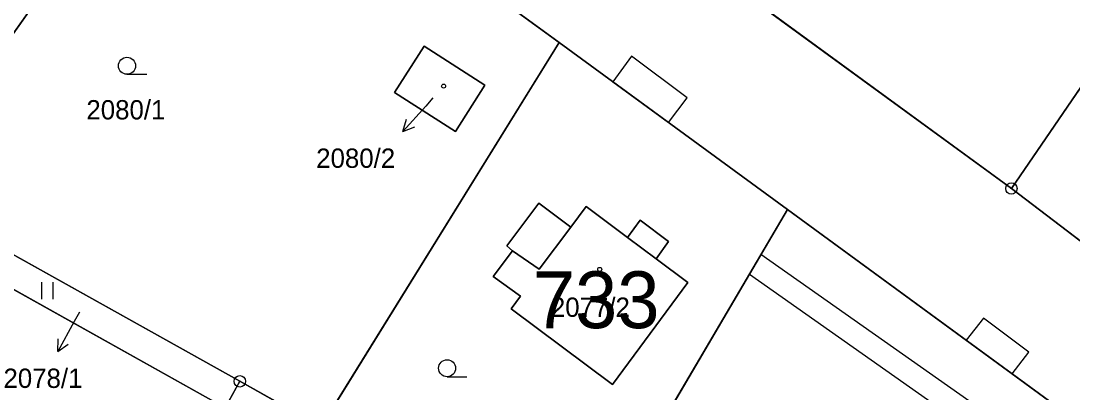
# Model space of a CAD drawing. Extents: x -689422 to -685210, y -987725 to -982160.
# Drawn here: x -687744.2 to -687651.6, y -985018.3 to -984985.6 of the extents above; entities that cross this region are included whole.
import ezdxf

# ---------------------------------------------------------------- set-up
doc = ezdxf.new("R2010")
doc.units = 0
for name, color, linetype in [('KN_Budovy', 7, 'Continuous'), ('KN_Budovy_cisla_domovni', 7, 'Continuous'), ('KN_Hranice_parcel', 7, 'Continuous'), ('KN_Hranice_parcel_vnitrni_kresba', 7, 'Continuous'), ('KN_Parcelni cisla', 7, 'Continuous'), ('KN_Parcelni cisla_sipky', 7, 'Continuous'), ('KN_Polygon parcely', 7, 'Continuous'), ('KN_POZEMKY_OSTATNI PLOCHA', 7, 'Continuous'), ('KN_POZEMKY_TTP', 7, 'Continuous'), ('KN_POZEMKY_ZAHRADA', 7, 'Continuous'), ('KN_POZEMKY_ZASTAVENA PLOCHA', 7, 'Continuous'), ('KN_VYUZITI_16_ostatni plocha_silnice', 7, 'Continuous'), ('KN_Věcná břemena k části', 7, 'Continuous'), ('KN_Značky bodu BP', 7, 'Continuous'), ('KN_Značky budov', 7, 'Continuous'), ('KN_Značky kultur', 7, 'Continuous')]:
    doc.layers.add(name, color=color, linetype=linetype)

msp = doc.modelspace()

# ---------------------------------------------------------------- linework, layer by layer
at = {"layer": 'KN_Budovy'}
for points in [[(-687711.29, -984991.84), (-687705.93, -984995.27), (-687703.33, -984991.22), (-687708.69, -984987.78)], [(-687690.78, -985004.6), (-687694.41, -985001.88), (-687695.77, -985003.69), (-687698.56, -985007.39), (-687700.9, -985005.77), (-687702.61, -985008.04), (-687700.21, -985009.76), (-687701.03, -985010.87), (-687692.1, -985017.54), (-687685.47, -985008.57), (-687688.27, -985006.48)]]:
    msp.add_lwpolyline(points, close=True, dxfattribs=at)
at = {"layer": 'KN_Hranice_parcel'}
for p, q in [((-687728.9, -984964.08), (-687696.81, -984987.44)), ((-687656.99, -985000.3), (-687686.61, -984978.67)), ((-687717.76, -985021.26), (-687696.81, -984987.44)), ((-687696.81, -984987.44), (-687676.7, -985002.14)), ((-687638.33, -985014.48), (-687656.99, -985000.3)), ((-687676.7, -985002.14), (-687693.14, -985030.09)), ((-687676.7, -985002.14), (-687634.28, -985033.15)), ((-687749.74, -985003.39), (-687724.91, -985017.26)), ((-687752.64, -985004.81), (-687726.19, -985019.59)), ((-687726.19, -985019.59), (-687724.91, -985017.26)), ((-687724.91, -985017.26), (-687717.76, -985021.26))]:
    msp.add_line(p, q, dxfattribs=at)
for points in [[(-687583.1, -984895.36), (-687627.09, -984956.62), (-687656.99, -985000.3)], [(-687728.9, -984964.08), (-687747.5, -984990.39), (-687749.54, -984993.51)], [(-687703.33, -984991.22), (-687705.93, -984995.27), (-687711.29, -984991.84), (-687708.69, -984987.78), (-687703.33, -984991.22)], [(-687701.03, -985010.87), (-687700.21, -985009.76), (-687702.61, -985008.04), (-687700.9, -985005.77), (-687701.4, -985005.35), (-687698.58, -985001.6), (-687695.77, -985003.69), (-687694.41, -985001.88), (-687690.78, -985004.6), (-687689.66, -985003.08), (-687687.16, -985004.95), (-687688.27, -985006.48), (-687685.47, -985008.57), (-687692.1, -985017.54), (-687701.03, -985010.87)]]:
    msp.add_lwpolyline(points, dxfattribs=at)
at = {"layer": 'KN_Hranice_parcel_vnitrni_kresba'}
for p, q in [((-687698.56, -985007.39), (-687695.77, -985003.69)), ((-687690.78, -985004.6), (-687688.27, -985006.48)), ((-687700.9, -985005.77), (-687698.56, -985007.39))]:
    msp.add_line(p, q, dxfattribs=at)
at = {"layer": 'KN_Parcelni cisla_sipky'}
for p, q in [((-687707.91, -984992.33), (-687708.54, -984993.04)), ((-687708.54, -984993.04), (-687710.548, -984995.27)), ((-687710.548, -984995.27), (-687710.25, -984994.191)), ((-687710.548, -984995.27), (-687709.506, -984994.861)), ((-687739.03, -985011.17), (-687739.49, -985012.01)), ((-687739.49, -985012.01), (-687740.945, -985014.635)), ((-687740.945, -985014.635), (-687740.897, -985013.516)), ((-687740.945, -985014.635), (-687740.021, -985014.002))]:
    msp.add_line(p, q, dxfattribs=at)
at = {"layer": 'KN_Polygon parcely'}
for points in [[(-687524.37, -984718.56), (-687513.26, -984643.33), (-687516.05, -984642.24), (-687526.38, -984637.98), (-687539.51, -984739.56), (-687556.05, -984788.06), (-687586.58, -984850.42), (-687599.51, -984866.59), (-687643.39, -984924.65), (-687686.61, -984978.67), (-687656.99, -985000.3), (-687627.09, -984956.62), (-687583.1, -984895.36), (-687562.57, -984862.29), (-687550.97, -984829.93), (-687533.16, -984761.41)], [(-687627.09, -984956.62), (-687656.99, -985000.3), (-687638.33, -985014.48), (-687632.36, -985006.77), (-687620.25, -985015.87), (-687551.59, -984918.2), (-687583.1, -984895.36)], [(-687728.9, -984964.08), (-687751.7, -984947.54), (-687755.71, -984944.63), (-687762.32, -984955.08), (-687771, -984974.71), (-687772.45, -984977.78), (-687766.26, -984982.03), (-687749.54, -984993.51), (-687747.5, -984990.39)], [(-687749.54, -984993.51), (-687745.07, -984996.58), (-687749.74, -985003.39), (-687724.91, -985017.26), (-687717.76, -985021.26), (-687696.81, -984987.44), (-687728.9, -984964.08), (-687747.5, -984990.39)], [(-687676.7, -985002.14), (-687696.81, -984987.44), (-687717.76, -985021.26), (-687694.81, -985029.49), (-687693.14, -985030.09)], [(-687703.33, -984991.22), (-687708.69, -984987.78), (-687711.29, -984991.84), (-687705.93, -984995.27)], [(-687703.33, -984991.22), (-687705.93, -984995.27), (-687711.29, -984991.84), (-687708.69, -984987.78)], [(-687701.03, -985010.87), (-687692.1, -985017.54), (-687685.47, -985008.57), (-687688.27, -985006.48), (-687687.16, -985004.95), (-687689.66, -985003.08), (-687690.78, -985004.6), (-687694.41, -985001.88), (-687695.77, -985003.69), (-687698.58, -985001.6), (-687701.4, -985005.35), (-687700.9, -985005.77), (-687702.61, -985008.04), (-687700.21, -985009.76)], [(-687701.03, -985010.87), (-687700.21, -985009.76), (-687702.61, -985008.04), (-687700.9, -985005.77), (-687701.4, -985005.35), (-687698.58, -985001.6), (-687695.77, -985003.69), (-687694.41, -985001.88), (-687690.78, -985004.6), (-687689.66, -985003.08), (-687687.16, -985004.95), (-687688.27, -985006.48), (-687685.47, -985008.57), (-687692.1, -985017.54)], [(-687679.93, -985039.52), (-687675.09, -985043.63), (-687653.89, -985061.65), (-687634.82, -985033.93), (-687634.28, -985033.15), (-687676.7, -985002.14), (-687693.14, -985030.09)], [(-687749.74, -985003.39), (-687752.64, -985004.81), (-687726.19, -985019.59), (-687724.91, -985017.26)], [(-687769.32, -985035.17), (-687742.77, -985049.76), (-687726.19, -985019.59), (-687752.64, -985004.81)], [(-687694.81, -985029.49), (-687717.76, -985021.26), (-687724.91, -985017.26), (-687726.19, -985019.59), (-687719.15, -985023.53), (-687695.77, -985031.23)]]:
    msp.add_lwpolyline(points, close=True, dxfattribs=at)
for points in [[(-687804.21, -984883.79), (-687794.59, -984897.73), (-687784.13, -984912.02), (-687779.78, -984917.32), (-687755.71, -984944.63), (-687751.7, -984947.54), (-687728.9, -984964.08), (-687696.81, -984987.44), (-687676.7, -985002.14), (-687634.28, -985033.15), (-687611.58, -985049.47), (-687605.06, -985055.05), (-687589.25, -985066.42), (-687569.9, -985081.12), (-687567.88, -985082.71), (-687545.22, -985101.04), (-687533.51, -985110)], [(-687530.18, -985097.82), (-687547.85, -985082.73), (-687585.79, -985054.04), (-687605.26, -985039.31), (-687625.62, -985023.92), (-687638.33, -985014.48), (-687656.99, -985000.3), (-687686.61, -984978.67), (-687731.63, -984947.48), (-687748.45, -984933.68), (-687764.19, -984917.52), (-687771.32, -984908.97), (-687778.07, -984899.31), (-687785.83, -984887.43)]]:
    msp.add_lwpolyline(points, dxfattribs=at)
at = {"layer": 'KN_POZEMKY_OSTATNI PLOCHA'}
for p, q in [((-687696.81, -984987.44), (-687728.9, -984964.08)), ((-687686.61, -984978.67), (-687656.99, -985000.3)), ((-687676.7, -985002.14), (-687696.81, -984987.44)), ((-687656.99, -985000.3), (-687638.33, -985014.48)), ((-687634.28, -985033.15), (-687676.7, -985002.14))]:
    msp.add_line(p, q, dxfattribs=at)
at = {"layer": 'KN_POZEMKY_TTP'}
for p, q in [((-687627.09, -984956.62), (-687656.99, -985000.3)), ((-687656.99, -985000.3), (-687627.09, -984956.62)), ((-687656.99, -985000.3), (-687686.61, -984978.67)), ((-687638.33, -985014.48), (-687656.99, -985000.3)), ((-687749.74, -985003.39), (-687724.91, -985017.26)), ((-687752.64, -985004.81), (-687726.19, -985019.59)), ((-687726.19, -985019.59), (-687752.64, -985004.81)), ((-687724.91, -985017.26), (-687726.19, -985019.59)), ((-687726.19, -985019.59), (-687724.91, -985017.26)), ((-687724.91, -985017.26), (-687717.76, -985021.26))]:
    msp.add_line(p, q, dxfattribs=at)
at = {"layer": 'KN_POZEMKY_ZAHRADA'}
for p, q in [((-687728.9, -984964.08), (-687747.5, -984990.39)), ((-687747.5, -984990.39), (-687728.9, -984964.08)), ((-687728.9, -984964.08), (-687696.81, -984987.44)), ((-687717.76, -985021.26), (-687696.81, -984987.44)), ((-687696.81, -984987.44), (-687717.76, -985021.26)), ((-687708.69, -984987.78), (-687711.29, -984991.84)), ((-687703.33, -984991.22), (-687708.69, -984987.78)), ((-687696.81, -984987.44), (-687676.7, -985002.14)), ((-687711.29, -984991.84), (-687705.93, -984995.27)), ((-687705.93, -984995.27), (-687703.33, -984991.22)), ((-687698.58, -985001.6), (-687701.4, -985005.35)), ((-687695.77, -985003.69), (-687698.58, -985001.6)), ((-687694.41, -985001.88), (-687695.77, -985003.69)), ((-687690.78, -985004.6), (-687694.41, -985001.88)), ((-687676.7, -985002.14), (-687693.14, -985030.09)), ((-687693.14, -985030.09), (-687676.7, -985002.14)), ((-687676.7, -985002.14), (-687634.28, -985033.15)), ((-687689.66, -985003.08), (-687690.78, -985004.6)), ((-687687.16, -985004.95), (-687689.66, -985003.08)), ((-687724.91, -985017.26), (-687749.74, -985003.39)), ((-687688.27, -985006.48), (-687687.16, -985004.95)), ((-687700.9, -985005.77), (-687702.61, -985008.04)), ((-687701.4, -985005.35), (-687700.9, -985005.77)), ((-687685.47, -985008.57), (-687688.27, -985006.48)), ((-687702.61, -985008.04), (-687700.21, -985009.76)), ((-687692.1, -985017.54), (-687685.47, -985008.57)), ((-687700.21, -985009.76), (-687701.03, -985010.87)), ((-687701.03, -985010.87), (-687692.1, -985017.54)), ((-687717.76, -985021.26), (-687724.91, -985017.26))]:
    msp.add_line(p, q, dxfattribs=at)
at = {"layer": 'KN_POZEMKY_ZASTAVENA PLOCHA'}
for p, q in [((-687711.29, -984991.84), (-687708.69, -984987.78)), ((-687708.69, -984987.78), (-687703.33, -984991.22)), ((-687705.93, -984995.27), (-687711.29, -984991.84)), ((-687703.33, -984991.22), (-687705.93, -984995.27)), ((-687701.4, -985005.35), (-687698.58, -985001.6)), ((-687698.58, -985001.6), (-687695.77, -985003.69)), ((-687695.77, -985003.69), (-687694.41, -985001.88)), ((-687694.41, -985001.88), (-687690.78, -985004.6)), ((-687690.78, -985004.6), (-687689.66, -985003.08)), ((-687689.66, -985003.08), (-687687.16, -985004.95)), ((-687687.16, -985004.95), (-687688.27, -985006.48)), ((-687702.61, -985008.04), (-687700.9, -985005.77)), ((-687700.9, -985005.77), (-687701.4, -985005.35)), ((-687688.27, -985006.48), (-687685.47, -985008.57)), ((-687700.21, -985009.76), (-687702.61, -985008.04)), ((-687685.47, -985008.57), (-687692.1, -985017.54)), ((-687701.03, -985010.87), (-687700.21, -985009.76)), ((-687692.1, -985017.54), (-687701.03, -985010.87))]:
    msp.add_line(p, q, dxfattribs=at)
at = {"layer": 'KN_VYUZITI_16_ostatni plocha_silnice'}
for p, q in [((-687696.81, -984987.44), (-687728.9, -984964.08)), ((-687686.61, -984978.67), (-687656.99, -985000.3)), ((-687676.7, -985002.14), (-687696.81, -984987.44)), ((-687656.99, -985000.3), (-687638.33, -985014.48)), ((-687634.28, -985033.15), (-687676.7, -985002.14))]:
    msp.add_line(p, q, dxfattribs=at)
at = {"layer": 'KN_Věcná břemena k části'}
for points in [[(-687692.07, -984990.9), (-687687.17, -984994.49), (-687685.52, -984992.31), (-687690.43, -984988.65)], [(-687635.82, -985032.7), (-687638.32, -985032.78), (-687648.71, -985025.85), (-687659.14, -985020.09), (-687679.04, -985006.11), (-687680.05, -985007.84), (-687660.2, -985021.79), (-687649.75, -985027.57), (-687638.9, -985034.8), (-687635.34, -985034.69), (-687634.82, -985033.93), (-687634.28, -985033.15), (-687635.37, -985032.35)], [(-687660.97, -985013.64), (-687656.93, -985016.59), (-687655.45, -985014.68), (-687659.45, -985011.71)]]:
    msp.add_lwpolyline(points, close=True, dxfattribs=at)
at = {"layer": 'KN_Značky bodu BP'}
for centre, radius in [((-687656.99, -985000.3), 0.5), ((-687656.99, -985000.3), 0.0303), ((-687724.91, -985017.26), 0.5), ((-687724.91, -985017.26), 0.0303)]:
    msp.add_circle(centre, radius, dxfattribs=at)
at = {"layer": 'KN_Značky budov'}
for centre in [(-687706.967, -984991.289), (-687693.227, -985007.409)]:
    msp.add_circle(centre, 0.175, dxfattribs=at)
at = {"layer": 'KN_Značky kultur'}
for p, q in [((-687734.843, -984990.25), (-687733.093, -984990.25)), ((-687742.351, -985010.04), (-687742.351, -985008.54)), ((-687741.35, -985010.04), (-687741.35, -985008.54)), ((-687706.663, -985016.86), (-687704.913, -985016.86))]:
    msp.add_line(p, q, dxfattribs=at)
for centre in [(-687734.843, -984989.5), (-687706.663, -985016.11)]:
    msp.add_circle(centre, 0.75, dxfattribs=at)

# ---------------------------------------------------------------- texts
at = {"layer": 'KN_Budovy_cisla_domovni'}
msp.add_text('733', height=5, dxfattribs=at).set_placement((-687699.121, -985012.584))
at = {"layer": 'KN_Parcelni cisla'}
for s, p in [('2080/1', (-687738.417, -984994.22)), ('2080/2', (-687718.187, -984998.48)), ('2077/2', (-687697.527, -985011.59)), ('2078/1', (-687745.717, -985017.84))]:
    msp.add_text(s, height=1.7, dxfattribs=at).set_placement(p)

doc.saveas('drawing.dxf')
